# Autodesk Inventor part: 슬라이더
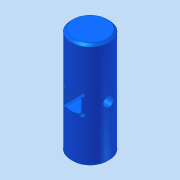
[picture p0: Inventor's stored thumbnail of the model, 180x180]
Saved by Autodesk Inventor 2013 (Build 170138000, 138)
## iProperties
Company: 한국ATC센터
Created: 2015-04
Part Number: 슬라이더
Document SubType Name: Modeling
Designer: KYOUNG IL JANG
Density: 1 g/cm^3
Material: 일반
Mass: 11.2119 g
Surface Area: 38.892 cm^2
Volume: 11.2119 cm^3
Author: KYOUNG IL JANG
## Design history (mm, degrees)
sketch "스케치1"
  geometry: C1 r 9 at (0, 0); 1 further point
  constraints: 1 centre point, 1 coincident
  dimensions: "d0" = 18 diameter of C1
extrude "돌출1" new body sketch "스케치1" stored distance "d1" = 50; taper "d2" = 0 deg
node "작업 평면1"
sketch "스케치3"
  geometry: L1 (4, 25)-(-4, 25); L2 (-4, 25)-(-4, -25); L3 (-4, -25)-(4, -25); L4 (4, -25)-(4, 25); 3 further points
  constraints: 8 end point, 2 midpoint, 2 parallel, 1 horizontal, 1 horizontal alignment, 1 perpendicular, 1 vertical alignment
  dimensions: "d5" = 8 distance of L1.start L1.end; "d6" = 50 distance of L1.end L2.end
extrude "돌출3" cut sketch "스케치3" stored distance "d7" = 8; taper "d8" = 0 deg
sketch "스케치4"
  geometry: 5 further points
hole "구멍1" sketch "스케치4" at (4, 4), (-4, 4), (-4, -4), (4, -4) diameter "d9" = 2; stored, may be unused: countersink angle "d13" = 90 deg, drill point angle "d15" = 118 deg; dims "d10" = 6, "d11" = 4, "d12" = 2, "d14" = 8
node "작업 평면2"
sketch "스케치5"
  geometry: 1 further point
hole "구멍2" sketch "스케치5" at (0, 0) diameter "d16" = 5; stored, may be unused: countersink angle "d20" = 90 deg, drill point angle "d22" = 118 deg; dims "d17" = 6, "d18" = 4, "d19" = 2, "d21" = 8
chamfer "모따기1" distance "d23" = 1; stored, may be unused: second distance "d24" = 2, angle "d25" = 45 deg
node "솔리드1"
mirror "대칭1"
